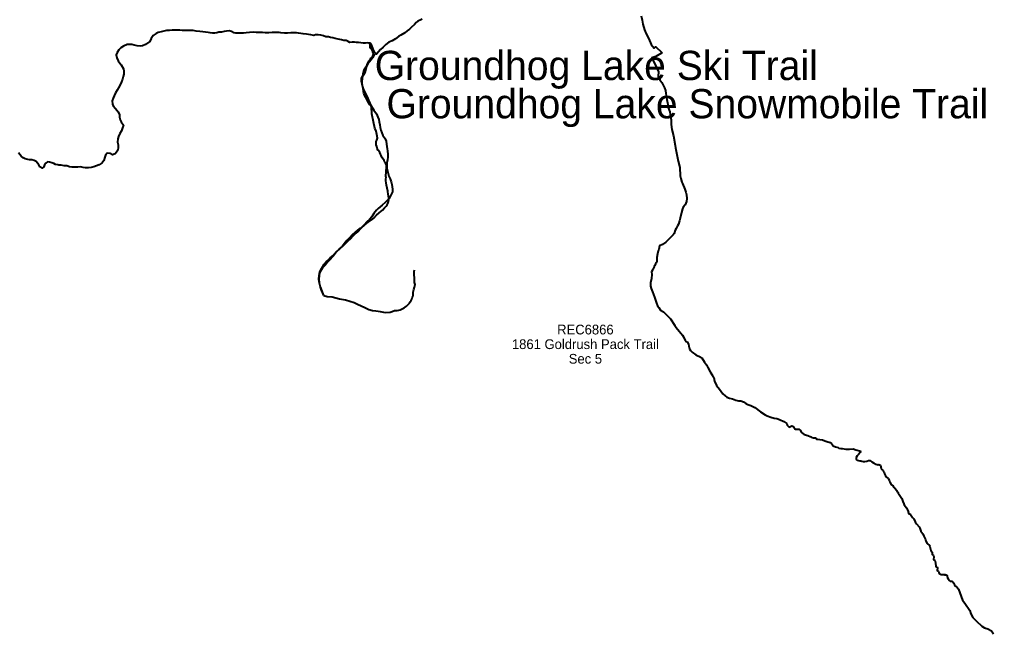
# Model space of a CAD drawing. Extents: x 322505 to 642419, y 5806860 to 5919753.
# Drawn here: x 594284 to 604282, y 5870637 to 5876927 of the extents above; entities that cross this region are included whole.
import ezdxf
from ezdxf.enums import TextEntityAlignment as Align

# ---------------------------------------------------------------- set-up
doc = ezdxf.new("R2010")
doc.units = 0
doc.header["$LTSCALE"] = 140
doc.layers.add('4', color=7, linetype='Continuous', lineweight=40)
doc.layers.add('5', color=7, linetype='Continuous', lineweight=40)

msp = doc.modelspace()

# ---------------------------------------------------------------- linework, layer by layer
at = {"layer": '4'}
for points in [[(600666.8, 5876964), (600675, 5876920.9), (600682.5, 5876878.3), (600700.2, 5876822.9), (600716.8, 5876779.4), (600742.8, 5876727.7), (600767.5, 5876669.9), (600797.8, 5876633.3), (600814.1, 5876647.2), (600876.7, 5876590.3), (600873.4, 5876583.4), (600815, 5876546.2), (600775.4, 5876534.6), (600828.1, 5876422.7), (600841.5, 5876391.2), (600841.2, 5876346.9), (600858, 5876307.9), (600878.8, 5876280.6), (600903.6, 5876225.5), (600913.7, 5876197.9), (600919.2, 5876168.8), (600928.5, 5876106.6), (600934, 5876071.4), (600941.3, 5876046.3), (600942.1, 5876023.2), (600958.7, 5875978.2), (600964, 5875952.6), (600971.5, 5875899.1), (600974.8, 5875849.2), (600981, 5875800.2), (600995.9, 5875731.9), (601014.8, 5875634.4), (601018.9, 5875610.7), (601028.9, 5875559.1), (601045.9, 5875475.2), (601062.2, 5875407.4), (601065.2, 5875323.8), (601070.7, 5875297), (601081.2, 5875258.3), (601088.5, 5875243), (601114, 5875185), (601122.3, 5875157), (601129.8, 5875127.6), (601133.9, 5875089.2), (601131.2, 5875060.6), (601115.2, 5875025.6), (601097.2, 5875002.3), (601088.2, 5874983.2), (601080, 5874945.9), (601066.9, 5874888.7), (601059.1, 5874860), (601047.5, 5874827.9), (601039.5, 5874809.7), (601025.8, 5874782.5), (601015.1, 5874766.8), (601005.3, 5874733), (600993.6, 5874717.7), (600971.6, 5874696.8), (600946.7, 5874670.8), (600918.7, 5874643.9), (600883.9, 5874618.3), (600854.9, 5874606.5), (600844.9, 5874568.9), (600838.3, 5874553.7), (600832.2, 5874522.6), (600826.3, 5874486.7), (600826.3, 5874445.7), (600819.3, 5874429.5), (600812.1, 5874418.8), (600806.5, 5874402.2), (600797.7, 5874391.5), (600793.7, 5874374.3), (600783.2, 5874355), (600772.1, 5874338.4), (600774.5, 5874310.7), (600770.7, 5874271.4)], [(598416.2, 5876929), (598402.6, 5876922.8), (598374, 5876910.6), (598356.8, 5876896.8), (598339.9, 5876876.7), (598304.3, 5876846.4), (598287.5, 5876827.6), (598264.5, 5876810.8), (598238.4, 5876792), (598199.6, 5876768), (598175.6, 5876754.4), (598142.1, 5876728.2), (598108.6, 5876708.3), (598076.2, 5876693.7), (598043.7, 5876672), (598016, 5876644.8), (597990.3, 5876617.7), (597948.9, 5876573.1), (597927.2, 5876593.4), (597920.6, 5876608.5), (597913.4, 5876623), (597900.3, 5876661.8), (597895.7, 5876668.3)], [(597895.7, 5876668.3), (597882, 5876683.3), (597882, 5876683.3), (597859.1, 5876686.7), (597835.7, 5876683.4), (597813.9, 5876685.3), (597788.9, 5876689.1), (597765, 5876692.5), (597742.1, 5876692.8), (597721.3, 5876695.6), (597698.9, 5876694.4), (597675.6, 5876692.7), (597675.6, 5876692.7), (597657.7, 5876702.7), (597637.3, 5876710.1), (597613.4, 5876712.5), (597587.9, 5876719.4), (597555.3, 5876726.2), (597523.7, 5876732.5), (597499.3, 5876738.4), (597474.9, 5876741.7), (597454, 5876748.2), (597428, 5876751), (597405.1, 5876760.4), (597377.1, 5876766.3), (597350.6, 5876770.6), (597323.7, 5876769.4), (597303.9, 5876764.3), (597275.9, 5876769.9), (597250.2, 5876774.4), (597230, 5876776.6), (597194.2, 5876780), (597172.9, 5876783.3), (597147.1, 5876785.6), (597125.9, 5876788.9), (597096.7, 5876788.9), (597067.6, 5876790.1), (597035.1, 5876785.6), (597004.9, 5876786.7), (596966.8, 5876790.1), (596948.9, 5876793.4), (596923.1, 5876793.4), (596900.7, 5876793.4), (596876.2, 5876795), (596842.7, 5876790.6), (596807.6, 5876790.3), (596778.1, 5876794.6), (596761.9, 5876794.5), (596742.8, 5876794.5), (596712.6, 5876794.5), (596689.1, 5876796.8), (596645.4, 5876792.3), (596609.9, 5876790.6), (596582.4, 5876788.3), (596562.1, 5876787.1), (596540.8, 5876785.9), (596505.7, 5876786.6), (596483.3, 5876791.5), (596483.3, 5876791.5), (596458.3, 5876805.5), (596435.9, 5876810.4), (596409.4, 5876809.2), (596384.1, 5876803.9), (596356.7, 5876796.5), (596331.3, 5876795.8), (596309, 5876792), (596287.7, 5876787.8), (596265.8, 5876788.1), (596242.4, 5876789.9), (596220, 5876794.8), (596193, 5876798.1), (596165.6, 5876799.9), (596133.5, 5876803.7), (596097.9, 5876808), (596064.8, 5876813.3), (596037.9, 5876814.1), (596006.9, 5876814.3), (595978.9, 5876815.1), (595955, 5876814.9), (595929.6, 5876816.2), (595902.1, 5876816.9), (595872.6, 5876818.2), (595850.8, 5876817), (595823.9, 5876814.2), (595793.4, 5876812.9), (595766, 5876808.1), (595737.1, 5876800.3), (595708.2, 5876792.4), (595687.4, 5876785.1), (595656.6, 5876764.5), (595636.9, 5876733.7), (595621, 5876700.6), (595575.6, 5876672.3), (595547.6, 5876655.9), (595524.6, 5876654.5), (595490.3, 5876656.9), (595461.3, 5876664.7), (595438.2, 5876670.3), (595409.4, 5876670.3), (595387.8, 5876670.3), (595350.1, 5876653.6)], [(595350.1, 5876653.6), (595323.8, 5876637.6), (595303.1, 5876617.6), (595285.1, 5876589), (595277.7, 5876563), (595282.5, 5876534.6), (595296.5, 5876504.8), (595313.5, 5876480), (595326.9, 5876461.9), (595351.1, 5876422.4), (595351.1, 5876422.4), (595355.9, 5876396.6), (595354.2, 5876367.6), (595349.3, 5876341.1), (595341.9, 5876313.6), (595331.5, 5876286.1), (595318, 5876257.5), (595301, 5876226.4), (595287, 5876203.4), (595270.5, 5876174.8), (595255.5, 5876144.2), (595244.5, 5876119.7), (595234.6, 5876091.7), (595239, 5876059.7), (595244.2, 5876039.9), (595270.9, 5876013.2), (595270.9, 5876013.2), (595298.1, 5875981.5), (595311.6, 5875948.6), (595311.8, 5875925.7), (595316.2, 5875896.3), (595327.5, 5875877.1), (595327.5, 5875877.1), (595350.2, 5875842.2), (595340.3, 5875814.2), (595329.8, 5875786.1), (595313.8, 5875759.1), (595299.4, 5875726.4), (595292.5, 5875703.5), (595290.7, 5875668.5), (595297.2, 5875641.2), (595295.9, 5875612.6), (595292, 5875586.7), (595280.5, 5875565.2), (595265.4, 5875548.8), (595239.5, 5875538.9), (595213.5, 5875550.9), (595184.5, 5875555.2), (595166.4, 5875536.8), (595159.4, 5875515.4), (595148.1, 5875480.7), (595131.5, 5875456.7), (595102.2, 5875436.1), (595075.8, 5875427.3), (595047.5, 5875415.3), (595020.1, 5875409.5), (594992.7, 5875405.7), (594961.7, 5875405.9), (594936.7, 5875409.8), (594908.7, 5875415.6), (594881.3, 5875413.4), (594853.4, 5875412.1), (594823.4, 5875412.4), (594795.9, 5875417.2), (594770.9, 5875424.1), (594741.4, 5875426.4), (594710.4, 5875431.7), (594686.5, 5875434), (594676.9, 5875435.3)], [(598025.5, 5875481.5), (598020.4, 5875491), (598007.2, 5875509.5), (597997.6, 5875533.5), (597989.6, 5875547), (597981.6, 5875563), (597969.6, 5875582), (597963.1, 5875588), (597953.6, 5875608), (597950.6, 5875625.5), (597943.9, 5875641.5), (597946.1, 5875674), (597952.6, 5875689.5), (597958, 5875710), (597952.6, 5875748), (597946.1, 5875781.5), (597929.8, 5875811), (597916.8, 5875876), (597901.6, 5875960.5), (597896.5, 5876030), (597880, 5876052), (597861, 5876085), (597840, 5876128), (597826, 5876151), (597819, 5876171), (597814, 5876189), (597811, 5876225), (597808, 5876235), (597803, 5876251), (597795, 5876295), (597796, 5876324), (597804, 5876344), (597820, 5876362), (597829, 5876377), (597835, 5876394), (597854, 5876465), (597863, 5876482), (597870, 5876499), (597886, 5876523), (597889, 5876531), (597911, 5876552), (597915, 5876560), (597916, 5876569), (597915, 5876579), (597907, 5876605), (597903, 5876614), (597886, 5876634), (597884, 5876642), (597885, 5876660), (597884, 5876670), (597880, 5876677), (597876, 5876679), (597876, 5876683)], [(594676.9, 5875435.3), (594654.9, 5875439.3), (594635.5, 5875448.8), (594614.1, 5875456.3), (594593.2, 5875464.2), (594570.3, 5875466), (594570.3, 5875466), (594553.1, 5875454.2), (594540.6, 5875434.8), (594533.1, 5875415.9), (594516.5, 5875403.1), (594516.5, 5875403.1), (594494, 5875416.1), (594494, 5875416.1), (594480.6, 5875435.8), (594469.3, 5875453.5), (594469.3, 5875453.5), (594454.4, 5875468.6), (594432.9, 5875479.6), (594409.5, 5875487), (594409.5, 5875487), (594387.6, 5875485.8), (594387.6, 5875485.8), (594367.8, 5875491.7), (594342.8, 5875499.1), (594320.4, 5875507.6), (594300.9, 5875524.1), (594286, 5875542.8), (594275.2, 5875560.5)], [(598071.5, 5875118), (598068.8, 5875130.5), (598063.9, 5875166), (598059.2, 5875197.5), (598052.1, 5875227.5), (598047.5, 5875252.5), (598045.7, 5875273), (598045.2, 5875290.5), (598047.2, 5875311), (598045.7, 5875317), (598045.6, 5875323.5), (598047.1, 5875360), (598047.9, 5875376.5), (598052.2, 5875400.5), (598051.4, 5875432.5), (598043.3, 5875447.5), (598039.2, 5875456), (598031.3, 5875467), (598025.8, 5875481), (598025.5, 5875481.5)], [(597407.5, 5874094), (597396.6, 5874118.5), (597383, 5874151), (597372, 5874179.5), (597366.1, 5874207.5), (597360.2, 5874236), (597358.1, 5874266.5), (597358.6, 5874295.5), (597361.6, 5874321), (597369.8, 5874346.5), (597380.7, 5874367), (597396.6, 5874391.5), (597411.1, 5874416), (597433.3, 5874440.5), (597451.9, 5874457.5), (597472.9, 5874481), (597502.7, 5874505.5), (597536, 5874542), (597564.5, 5874569.5), (597601.7, 5874603), (597632.6, 5874633), (597661.1, 5874659), (597682.2, 5874677.5), (597709.4, 5874706), (597729.1, 5874728), (597756.6, 5874748), (597796.1, 5874788), (597827, 5874820.5), (597861.9, 5874847), (597893.1, 5874868), (597920.4, 5874890), (597948.9, 5874918.5), (597977.4, 5874945), (598008.4, 5874969.5), (598031.9, 5874994.5), (598048, 5875011), (598056.4, 5875026.5), (598067.4, 5875046), (598076.6, 5875080.5), (598074.9, 5875094), (598071.7, 5875117), (598071.5, 5875118)], [(598108.6, 5873931.5), (598131.6, 5873940), (598146.6, 5873940.5), (598161.4, 5873942.5), (598176.2, 5873945.5), (598190.6, 5873949.5), (598204.7, 5873954.5), (598218.4, 5873961), (598231.5, 5873968), (598244.1, 5873976), (598255.9, 5873985.5), (598267.1, 5873995.5), (598277.5, 5874006), (598287, 5874018), (598295.6, 5874030), (598303.2, 5874043), (598309.9, 5874056.5), (598315.5, 5874070.5), (598320, 5874084.5), (598323.4, 5874099), (598325.7, 5874114), (598326, 5874129), (598327.9, 5874144), (598331.4, 5874158.5), (598339.8, 5874179.5), (598344, 5874209), (598338.4, 5874229), (598339.2, 5874244), (598336.9, 5874281), (598336.2, 5874305), (598335.9, 5874317.5), (598333.9, 5874340), (598338.2, 5874358.5)], [(600770.7, 5874271.4), (600762, 5874224.7), (600759.7, 5874191.5), (600766.7, 5874166.9), (600780, 5874131.8), (600802.6, 5874079.4), (600821.4, 5874017.2), (600832.8, 5873989.1), (600846.4, 5873972.3), (600864.1, 5873944.3), (600895.7, 5873928.5), (600908.6, 5873913.2), (600921.3, 5873898.8), (600946.3, 5873877.6), (600966.6, 5873855), (601009.8, 5873786.5), (601023.4, 5873765.5), (601054.8, 5873727.8), (601089.5, 5873686.8), (601099.7, 5873671.8), (601103.5, 5873660.3), (601116.5, 5873635.4), (601125.7, 5873622.5), (601136.5, 5873619.1), (601152.5, 5873597.3), (601155.5, 5873575.7), (601160.4, 5873549), (601171.7, 5873531.6), (601190.3, 5873514.4), (601225.9, 5873485.7), (601240.6, 5873479.9), (601262.3, 5873470.3), (601286.5, 5873454.2), (601316.7, 5873411.6), (601335.2, 5873384.9), (601350.3, 5873356.8), (601373.4, 5873313.2), (601397.2, 5873275.1), (601410.9, 5873252.3), (601419, 5873217.1), (601437, 5873173.6), (601470.8, 5873135.5), (601504.7, 5873088), (601527.1, 5873065.2), (601544.1, 5873052.7), (601572.4, 5873043), (601601.4, 5873036.8), (601638.1, 5873020.1), (601662.7, 5873015.5), (601687.9, 5873015), (601714.6, 5873003.3), (601740.3, 5872986), (601761.3, 5872977.4), (601790.9, 5872966.7), (601832.9, 5872945.3), (601888.7, 5872902.5), (601937.8, 5872872.4), (601957.8, 5872860.6), (601995.8, 5872846.1), (602031.5, 5872835.9), (602059.2, 5872834.7), (602083.5, 5872822), (602130.8, 5872802.7), (602161.9, 5872780.3), (602164, 5872765.4), (602183.9, 5872744.7), (602212.3, 5872757.9), (602219.2, 5872755.8), (602233.3, 5872744.2), (602246.8, 5872725.1), (602283.6, 5872722.7), (602295.6, 5872714.8), (602312.4, 5872690.2), (602338.4, 5872668.1), (602375, 5872658.3), (602405.5, 5872644.6), (602417.7, 5872638.8), (602431, 5872635.3), (602443, 5872636.4), (602454.1, 5872635.8), (602457.9, 5872628.5), (602465.7, 5872622), (602479.4, 5872620.5), (602500.1, 5872618.6), (602525.6, 5872612.9), (602551, 5872604.5), (602572.1, 5872598.4), (602603.6, 5872587.2), (602618, 5872578.5), (602629, 5872563.4), (602635.9, 5872552.8), (602658.7, 5872544.3), (602686.1, 5872534.9), (602694.8, 5872527.5), (602714, 5872526.7), (602729.2, 5872524.6), (602765.4, 5872517), (602802.6, 5872519), (602840.3, 5872521.2), (602867.8, 5872513.5), (602920.1, 5872497.8)], [(597407.5, 5874094), (597440.8, 5874086.5), (597493, 5874082), (597530.1, 5874072.5), (597569.9, 5874060), (597631.2, 5874052.5), (597718.4, 5874025), (597754.6, 5874005.5), (597790.6, 5873990), (597828.1, 5873971), (597869.3, 5873950.5), (597907.7, 5873943), (597940.9, 5873938.5), (597965.1, 5873934), (597985.5, 5873930)], [(597985.5, 5873930), (598020.1, 5873923), (598044.4, 5873920), (598088.8, 5873923.5), (598108.6, 5873931.5)], [(602920.1, 5872497.8), (602912.4, 5872485.8), (602894.9, 5872462.7), (602883.8, 5872450.2), (602873.4, 5872434.3), (602872.4, 5872418.7), (602879.3, 5872408.1), (602883.8, 5872406.1), (602910, 5872400), (602921.3, 5872397.9), (602931.6, 5872394.5), (602943, 5872391.7), (602959.6, 5872392), (602983.3, 5872395), (602998.6, 5872401.6), (603004.9, 5872403.4), (603013.4, 5872400.9), (603033.6, 5872388.5), (603049.3, 5872378.3), (603073.3, 5872365.5), (603087.4, 5872360.6), (603096.3, 5872358), (603105, 5872360.2), (603113.2, 5872359.6), (603120.9, 5872354.7), (603128, 5872320.9), (603129.6, 5872316.9), (603139.1, 5872304.9), (603148.4, 5872300.2), (603150.7, 5872296.9), (603158.5, 5872283.3), (603163.9, 5872264.8), (603172.9, 5872244.7), (603181.4, 5872235.6), (603202.1, 5872216.1)], [(603202.1, 5872216.1), (603215.3, 5872192.6), (603216.9, 5872179.3), (603232, 5872156.2), (603238.7, 5872153.7), (603245.6, 5872149.6), (603260.1, 5872125.3), (603267.6, 5872119.2), (603289, 5872095.8), (603288.8, 5872089.2), (603292.3, 5872082.2), (603303.1, 5872072.6), (603304.3, 5872066.7), (603312, 5872053.9), (603326.6, 5872031.7), (603339.7, 5872013.6), (603344.3, 5872001.2), (603351.7, 5871982.8), (603361.5, 5871956.7), (603365.7, 5871946.9), (603387.1, 5871917.2), (603394.2, 5871904), (603407.3, 5871877.5), (603409.2, 5871869.8), (603406.2, 5871863.6), (603408.1, 5871859.1), (603413.4, 5871856.5), (603419.1, 5871856.2), (603431.4, 5871850), (603449.9, 5871815.9), (603463.1, 5871803.7), (603479.3, 5871772), (603492.7, 5871753.2), (603517.4, 5871722.1), (603524.2, 5871707), (603536.7, 5871678.1), (603555.8, 5871651.6), (603565.6, 5871625.6), (603584, 5871591.2), (603588.4, 5871576.3), (603600.8, 5871551.1), (603625.5, 5871530.1), (603628.7, 5871520.2), (603634.3, 5871494.1), (603638.4, 5871478.1), (603653.4, 5871462.5), (603653.7, 5871437.9), (603665.9, 5871426.4), (603670.7, 5871415.3), (603666.7, 5871388.1), (603678.3, 5871378.9), (603687.1, 5871353.1), (603689.7, 5871315), (603695.2, 5871310.9), (603702, 5871307.9), (603708.1, 5871302.1), (603708.3, 5871299.3), (603706.5, 5871295.2), (603702.1, 5871278.3), (603704.8, 5871274.1), (603711, 5871271.3), (603718.8, 5871266.7), (603719.4, 5871254.6), (603725.3, 5871242.6), (603731.1, 5871240.4), (603732.6, 5871240), (603734.5, 5871236.6), (603736.7, 5871236.8), (603738.6, 5871236.6), (603745.9, 5871230.3), (603748.4, 5871231.3), (603749.4, 5871232.5), (603750.7, 5871233.7), (603752.4, 5871234.2), (603757, 5871233.6), (603760.2, 5871231.1), (603765.7, 5871231.8), (603766.6, 5871232.7), (603768.2, 5871233.5), (603775.7, 5871232.6), (603780.7, 5871230.3), (603783.3, 5871229.4), (603784.4, 5871229.5), (603785.2, 5871231.1), (603786.8, 5871231.5), (603789.2, 5871230.5), (603790.7, 5871229.2), (603793.3, 5871228.5), (603793.6, 5871229.4), (603795.2, 5871229.3), (603799.8, 5871227), (603802.4, 5871226), (603804.4, 5871224.4), (603805.6, 5871222), (603805.7, 5871220.4), (603805.6, 5871217.6), (603806.9, 5871216.3), (603805.5, 5871213.2), (603804.9, 5871209.9), (603805, 5871208), (603806.2, 5871206.2)], [(603806.2, 5871206.2), (603816.2, 5871187.1), (603830.7, 5871170.5), (603837.7, 5871163.1), (603853.1, 5871165.3), (603860.6, 5871162.3), (603870.1, 5871145.7), (603881.2, 5871126.3), (603889.8, 5871117), (603901.1, 5871110.6), (603923, 5871083)], [(603923, 5871083), (603963, 5870970), (603989, 5870938), (604038, 5870864), (604048, 5870829), (604070, 5870790), (604109, 5870753), (604162, 5870703), (604190, 5870686), (604224, 5870675), (604262, 5870655), (604282, 5870623)]]:
    msp.add_lwpolyline(points, dxfattribs=at)
at = {"layer": '5'}
for points in [[(597938.7, 5876578.5), (597933.1, 5876572.3), (597916.5, 5876550.8), (597906, 5876533.4), (597893, 5876514), (597875.9, 5876491.5), (597860.8, 5876472.6), (597846.3, 5876449), (597833.7, 5876429.1), (597819.7, 5876407.2), (597810.3, 5876382.7), (597805, 5876345.5), (597802.2, 5876320.1), (597798.4, 5876290.1), (597798.6, 5876262.7), (597806, 5876234.8), (597812.8, 5876215), (597828.8, 5876181.6), (597839.7, 5876161.9), (597857.3, 5876126), (597867.1, 5876101.2), (597880.1, 5876070.3), (597894.1, 5876040.9), (597909.1, 5876013.6), (597922, 5875995.4), (597949.7, 5875958.6), (597962.7, 5875926.7), (597971.6, 5875902.4), (597977.4, 5875878.5), (597983.8, 5875845.6), (597987.6, 5875819.7), (597992.9, 5875791.8), (598001.8, 5875763.4), (598014.7, 5875736.6), (598033.8, 5875709.3), (598049.3, 5875680), (598052.1, 5875648), (598054.9, 5875624.7), (598058.1, 5875599.3), (598060.3, 5875578.5), (598065.7, 5875542.9), (598065, 5875514.5), (598060.6, 5875487), (598055.3, 5875455.4), (598053.5, 5875432.1), (598055.3, 5875403.1), (598061.1, 5875375.2), (598067.5, 5875347.8), (598075.8, 5875321), (598087.8, 5875293.6), (598100.3, 5875261.7), (598106.6, 5875233.8), (598109.9, 5875210.5), (598113.9, 5875186.9), (598111, 5875158.5), (598078.7, 5875090.5), (598057.2, 5875070.5), (598035.7, 5875050), (598005.3, 5875022.1), (597985.8, 5875004), (597966.2, 5874988.9), (597947.3, 5874970.3), (597919.7, 5874935.5), (597900.6, 5874902.3), (597877, 5874876.1), (597848.8, 5874849.5), (597822.1, 5874819.3), (597822.1, 5874819.3), (597795.1, 5874794.3)], [(597783.3, 5874788.4), (597752.4, 5874764.8), (597726.2, 5874740.7), (597699, 5874716.6), (597668.8, 5874684.3), (597643.6, 5874658.7), (597617.4, 5874626.4), (597595.3, 5874597.3), (597567.6, 5874571.6), (597539.4, 5874542.9), (597517.3, 5874516.3), (597504.7, 5874500.4), (597490.6, 5874485.6), (597476.5, 5874469.7), (597446.8, 5874435.9), (597420.1, 5874407.7), (597394.5, 5874380.1), (597373.4, 5874345.7), (597364.5, 5874326.8), (597359.4, 5874297.1), (597357, 5874265.7), (597359.4, 5874224.5), (597369, 5874183.4), (597397.6, 5874111.9)]]:
    msp.add_lwpolyline(points, dxfattribs=at)

# ---------------------------------------------------------------- texts
at = {"layer": '4'}
for s, p in [('REC6866', (600092.7, 5873695.9)), ('1861 Goldrush Pack Trail', (600092.7, 5873545.9)), ('Sec 5', (600092.7, 5873395.9))]:
    msp.add_text(s, height=100, dxfattribs=at).set_placement(p, align=Align.CENTER)
at = {"layer": '5'}
for s, p in [('Groundhog Lake Ski Trail', (597930, 5876305.8)), ('Groundhog Lake Snowmobile Trail', (598050.5, 5875913.3))]:
    msp.add_text(s, height=300, dxfattribs=at).set_placement(p)

doc.saveas('drawing.dxf')
